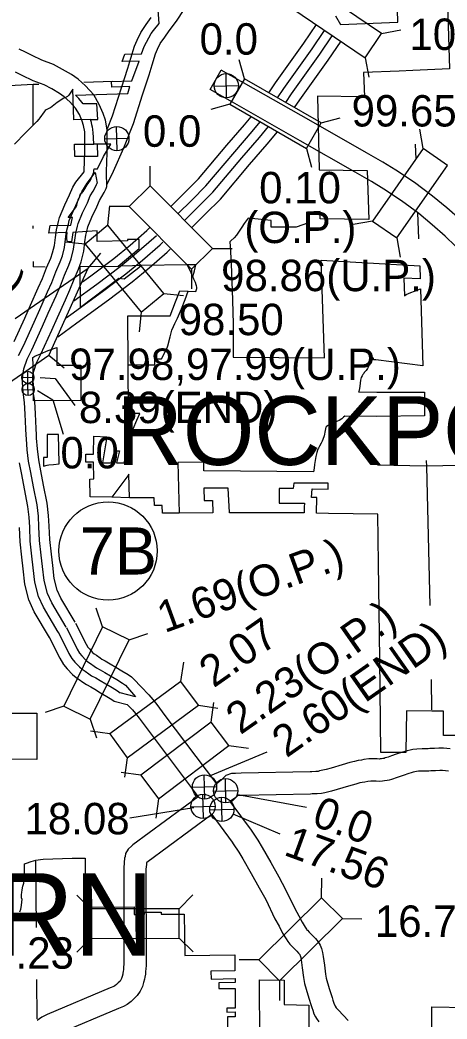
# Model space of a CAD drawing. Extents: x 369523 to 838377, y 495025 to 936819.
# Drawn here: x 655053 to 666534, y 860745 to 887609 of the extents above; entities that cross this region are included whole.
import ezdxf

# ---------------------------------------------------------------- set-up
doc = ezdxf.new("R2010")
doc.units = 0
for name, color, linetype in [('DSN_BRDG_Annotation', 7, 'Continuous'), ('DSN_DRFT_Common-Annotations', 7, 'Continuous'), ('DSN_DRFT_Common-Line', 7, 'Continuous'), ('DSN_DRFT_Junk-No-Plot', 7, 'Continuous'), ('Level 1', 7, 'Continuous'), ('Level 11', 7, 'Continuous'), ('Level 15', 7, 'Continuous'), ('Level 2', 7, 'Continuous'), ('Level 21', 7, 'Continuous'), ('Level 22', 7, 'Continuous'), ('Level 23', 7, 'Continuous')]:
    doc.layers.add(name, color=color, linetype=linetype)

msp = doc.modelspace()

# ---------------------------------------------------------------- linework, layer by layer
at = {"layer": 'DSN_BRDG_Annotation'}
for p, q in [((660171, 867293), (661699, 867933)), ((662759, 866430), (660911, 866775)), ((658003, 866159), (659728, 866430)), ((662044, 865715), (660787, 866258))]:
    msp.add_line(p, q, dxfattribs=at)
for points in [[(655592, 877992), (655997, 877970), (656531, 877244)], [(655527, 877650), (655933, 877393), (656211, 876475)]]:
    msp.add_lwpolyline(points, dxfattribs=at)
at = {"layer": 'DSN_DRFT_Common-Annotations'}
for p, q in [((660607, 885514), (660592, 886165)), ((660274, 885832), (660925, 885847)), ((657666, 884095), (657651, 884746)), ((657333, 884413), (657984, 884428)), ((655102, 877995), (655427, 878002)), ((655268, 877836), (655261, 878161)), ((655108, 877667), (655434, 877675)), ((655275, 877508), (655267, 877834)), ((660023, 866662), (660008, 867313)), ((660590, 866558), (660575, 867209)), ((659690, 866980), (660341, 866995)), ((659984, 866137), (659969, 866788)), ((660257, 866876), (660908, 866891)), ((660489, 866056), (660474, 866707)), ((659651, 866455), (660302, 866470)), ((660156, 866374), (660807, 866389))]:
    msp.add_line(p, q, dxfattribs=at)
for centre, radius in [((660599, 885840), 326), ((657658, 884421), 326), ((655265, 877999), 163), ((655271, 877671), 163), ((660015, 866987), 326), ((660583, 866884), 326), ((659976, 866463), 326), ((660481, 866381), 326)]:
    msp.add_circle(centre, radius, dxfattribs=at)
at = {"layer": 'DSN_DRFT_Common-Line'}
msp.add_circle((657422, 873331), 1320, dxfattribs=at)
at = {"layer": 'Level 1'}
for points in [[(657390, 883173), (657564, 883546), (657845, 884175), (658101, 884825), (658351, 885598), (658526, 886135), (658607, 886407), (658699, 886700), (658751, 886822), (658825, 886976), (658943, 887149), (659062, 887321), (659265, 887577), (659471, 887889)], [(657402, 884687), (657536, 885028), (657781, 885783), (657953, 886313), (658033, 886583), (658136, 886908), (658204, 887070), (658304, 887277), (658448, 887488), (658579, 887678)], [(660694, 866594), (661272, 865823), (661302, 865766), (661445, 865557), (661566, 865353), (661795, 864958), (662012, 864565), (662193, 864229), (662442, 863719), (662551, 863521), (662636, 863348), (662719, 863215), (662753, 863160), (662760, 863151), (662780, 863132), (662828, 863083), (662926, 862986), (662995, 862912), (663070, 862823), (663123, 862727), (663158, 862641), (663188, 862531), (663207, 862425), (663236, 862194), (663265, 861954), (663285, 861844), (663370, 861562), (663399, 861456), (663444, 861321), (663466, 861251), (663495, 861173), (663514, 861109), (663515, 861108), (663526, 861091), (663556, 861048), (663621, 860979), (663876, 860708)], [(660208, 866242), (660762, 865502), (660786, 865456), (660939, 865234), (661048, 865049), (661273, 864662), (661485, 864277), (661659, 863955), (661909, 863443), (662019, 863244), (662112, 863055), (662210, 862899), (662254, 862827), (662305, 862757), (662358, 862705), (662404, 862659), (662496, 862567), (662545, 862515), (662573, 862482), (662581, 862467), (662588, 862450), (662602, 862400), (662613, 862334), (662640, 862121), (662672, 861865), (662701, 861704), (662794, 861396), (662825, 861282), (662873, 861138), (662898, 861057), (662927, 860980), (662954, 860888), (662995, 860806), (663029, 860755), (663086, 860672)]]:
    msp.add_lwpolyline(points, dxfattribs=at)
at = {"layer": 'Level 11'}
for points in [[(657377, 883498), (657391, 883823), (657394, 884001), (657400, 884154), (657398, 884309), (657395, 884434), (657393, 884659), (657348, 884916), (657291, 885096), (657186, 885339), (657035, 885598), (656816, 885838), (656616, 886017), (656440, 886141), (656200, 886281), (655950, 886413), (655644, 886526), (655379, 886654), (655198, 886748), (655032, 886823)], [(666763, 881526), (666487, 881792), (666138, 882103), (665773, 882403), (665312, 882746), (664838, 883064), (664506, 883267), (664067, 883516), (662584, 884363), (660768, 885399), (660169, 885739), (660465, 886261)], [(666895, 882232), (666529, 882559), (666143, 882875), (665658, 883237), (665161, 883569), (664811, 883784), (664365, 884038), (662881, 884884), (661065, 885920), (660465, 886261)], [(656778, 883523), (656791, 883841), (656794, 884019), (656800, 884163), (656798, 884297), (656795, 884424), (656793, 884604), (656763, 884773), (656728, 884887), (656650, 885068), (656549, 885240), (656393, 885411), (656242, 885547), (656116, 885636), (655909, 885756), (655705, 885864), (655409, 885973), (655111, 886118), (654936, 886207)], [(656551, 883246), (656778, 883523)], [(656857, 883221), (657077, 883511), (657126, 883221)], [(657386, 883132), (657377, 883498)], [(654897, 878968), (655179, 879594), (655332, 879939), (655545, 880407), (655655, 880659), (655767, 880944), (655878, 881205), (655929, 881344), (655980, 881547), (656008, 881756), (656037, 881968), (656087, 882186), (656115, 882302), (656259, 882637), (656386, 882909), (656473, 883117), (656551, 883246)], [(655011, 878589), (655145, 878849), (655430, 879482), (655583, 879827), (655796, 880295), (655910, 880553), (656021, 880840), (656134, 881104), (656192, 881263), (656250, 881494), (656281, 881719), (656308, 881919), (656354, 882123), (656377, 882215), (656510, 882524), (656638, 882797), (656719, 882992), (656857, 883221)], [(656297, 871278), (655905, 871933), (655791, 872190), (655700, 872538), (655659, 872909), (655622, 873218), (655580, 873617), (655564, 873984), (655548, 874265), (655513, 874569), (655418, 875052), (655345, 875437), (655284, 875744), (655248, 876052), (655225, 876347), (655218, 876441), (655209, 876615), (655193, 877008), (655178, 877319), (655147, 877527), (655130, 877708), (655121, 877885), (655126, 878059), (655158, 878233), (655242, 878492), (655370, 878740), (655658, 879380), (655811, 879724), (656024, 880193), (656141, 880458), (656253, 880746), (656366, 881013), (656431, 881190), (656496, 881447), (656528, 881685), (656554, 881874), (656598, 882066), (656615, 882135), (656738, 882422), (656866, 882696), (656943, 882879), (657018, 883003), (657071, 883101), (657112, 883182), (657126, 883221)], [(656533, 871419), (656149, 872060), (656051, 872281), (655971, 872588), (655932, 872940), (655896, 873249), (655854, 873638), (655839, 873998), (655823, 874288), (655785, 874612), (655688, 875104), (655615, 875489), (655556, 875786), (655522, 876079), (655499, 876367), (655493, 876457), (655484, 876628), (655468, 877020), (655452, 877346), (655420, 877560), (655404, 877727), (655397, 877888), (655400, 878031), (655425, 878165), (655497, 878386), (655618, 878620), (655910, 879268), (656062, 879612), (656275, 880081), (656395, 880352), (656508, 880642), (656622, 880911), (656694, 881109), (656766, 881394), (656801, 881647), (656825, 881825), (656865, 882003), (656876, 882048), (656989, 882309), (657118, 882584), (657189, 882754), (657256, 882866), (657315, 882972), (657367, 883075), (657386, 883132)], [(656083, 871149), (655682, 871818), (655554, 872107), (655453, 872492), (655410, 872880), (655374, 873190), (655330, 873599), (655314, 873972), (655299, 874244), (655266, 874531), (655172, 875005), (655100, 875389), (655037, 875705)], [(655847, 871008), (655438, 871691), (655294, 872016), (655182, 872442), (655137, 872849), (655100, 873160), (655056, 873578), (655040, 873958)], [(656302, 871269), (656589, 870692), (656651, 870584), (656714, 870512), (656819, 870399), (656880, 870350), (656948, 870301), (657045, 870233), (657108, 870188), (657210, 870138), (657336, 870063), (657487, 869970), (657655, 869873), (657811, 869778), (657889, 869723)], [(656548, 871391), (656831, 870822), (656875, 870744), (656918, 870696), (657007, 870601), (657047, 870569), (657108, 870525), (657205, 870457), (657250, 870425), (657341, 870380), (657479, 870298), (657629, 870205), (657795, 870109), (657961, 870008), (658048, 869947)], [(655832, 871035), (656125, 870445), (656221, 870276), (656326, 870158), (656461, 870013), (656563, 869932), (656644, 869873), (656741, 869805), (656838, 869736), (656960, 869676), (657064, 869614), (657218, 869519), (657387, 869421), (657523, 869338), (657587, 869294)], [(656078, 871158), (656368, 870575), (656446, 870437), (656529, 870343), (656649, 870215), (656729, 870151), (656803, 870098), (656900, 870029), (656979, 869972), (657091, 869918), (657207, 869849), (657359, 869755), (657527, 869657), (657674, 869569), (657745, 869518)], [(658048, 869947), (658375, 869613)], [(657889, 869723), (658157, 869408), (657745, 869518)], [(658375, 869613), (658455, 869529), (658485, 869498), (658521, 869463), (658622, 869339), (658731, 869205), (658951, 868906), (660334, 867073)], [(657587, 869294), (657938, 869203)], [(657938, 869203), (658022, 869114), (658061, 869073), (658078, 869057), (658156, 868961), (658256, 868838), (658470, 868547), (659848, 866721)], [(666619, 868006), (666441, 868028), (666317, 868026), (666197, 868019), (666076, 868015), (666023, 868013), (665962, 868012), (665870, 868010), (665719, 868005), (665615, 867993), (665545, 867979), (665463, 867960), (665397, 867939), (665334, 867921), (665166, 867865), (665045, 867823), (664948, 867787), (664916, 867777), (664875, 867764), (664842, 867755), (664813, 867749), (664772, 867742), (664740, 867739), (664718, 867737), (664660, 867742), (664553, 867745), (664428, 867743), (664298, 867721), (664231, 867709), (664145, 867698), (664044, 867674), (663919, 867642), (663715, 867579), (663417, 867493), (663283, 867454), (663110, 867415), (663067, 867404), (663005, 867399), (662897, 867396), (662853, 867395), (661003, 867355), (660851, 867348), (660742, 867343), (660591, 867289), (660466, 867168), (660334, 867073)], [(666572, 867407), (666409, 867427), (666337, 867426), (666222, 867420), (666102, 867416), (666044, 867413), (665973, 867412), (665885, 867410), (665764, 867406), (665710, 867400), (665672, 867392), (665622, 867381), (665569, 867364), (665509, 867347), (665359, 867297), (665249, 867259), (665144, 867220), (665096, 867205), (665042, 867188), (664979, 867171), (664921, 867159), (664855, 867148), (664802, 867142), (664720, 867134), (664626, 867143), (664550, 867145), (664483, 867143), (664401, 867130), (664321, 867115), (664251, 867107), (664189, 867092), (664083, 867064), (663886, 867004), (663583, 866916), (663432, 866873), (663246, 866830), (663162, 866810), (663040, 866800), (662912, 866796), (662864, 866795), (661022, 866755), (660897, 866750), (660852, 866706), (660694, 866594)], [(659848, 866721), (658090, 865427), (658060, 865401), (657964, 865315), (657893, 865195), (657877, 865115), (657864, 865073), (657855, 864953), (657841, 864802), (657847, 862386), (657844, 862221), (657839, 862136), (657834, 862080), (657830, 862024), (657822, 861976), (657817, 861951), (657801, 861892), (657784, 861835), (657767, 861800), (657743, 861766), (657696, 861717), (657646, 861669), (657606, 861638), (657580, 861623), (657480, 861584), (655784, 860871), (655697, 860826), (655644, 860791), (655518, 860705)], [(660208, 866242), (658460, 864954), (658457, 864951), (658453, 864903), (658441, 864774), (658447, 862381), (658444, 862197), (658437, 862090), (658432, 862033), (658426, 861953), (658413, 861872), (658403, 861817), (658378, 861727), (658346, 861619), (658286, 861492), (658205, 861380), (658122, 861294), (658038, 861212), (657936, 861136), (657840, 861081), (657706, 861028), (656040, 860328)]]:
    msp.add_lwpolyline(points, dxfattribs=at)
at = {"layer": 'Level 15'}
for points in [[(655560, 885878), (655403, 885871), (654922, 885847), (649866, 885610), (649393, 885593), (647659, 885500)], [(657548, 885959), (656772, 885927)]]:
    msp.add_lwpolyline(points, dxfattribs=at)
at = {"layer": 'Level 2'}
for points in [[(663536, 887724), (663666, 887491), (665211, 887547), (665176, 888868)], [(666524, 888911), (666599, 886299), (665612, 886250), (665246, 886232), (664293, 886201)], [(657022, 884599), (657016, 884636), (657010, 884674), (657002, 884724), (656989, 884789), (656977, 884849), (656953, 884929), (657143, 884929), (657121, 885358), (656754, 885352), (656718, 885403), (656637, 885501), (656549, 885585), (657949, 885631), (658002, 885817), (657522, 885801), (657517, 885951), (658061, 885973), (658258, 886504), (657803, 886497), (657871, 886689), (658324, 886702), (658353, 886798), (658393, 886895), (658579, 887243), (658643, 887322), (658796, 887517), (658712, 888610)], [(664293, 886201), (664316, 885546), (663048, 885562), (663095, 883581), (664387, 883565), (664434, 882244), (663126, 882261), (663122, 882458), (662779, 882443), (662806, 882152), (662474, 882037), (661810, 882040), (661807, 882218), (661191, 882283), (661079, 882136), (661022, 882040), (660871, 881827), (660811, 881750), (660724, 881667), (660695, 881641), (660705, 881525), (660731, 881051), (660767, 880084), (660774, 879734), (660781, 879457), (660784, 878787), (660781, 878541), (663238, 878527), (663153, 881147), (665805, 880996), (665816, 880646), (665373, 880671), (665395, 880195), (665439, 880225), (665559, 880280), (665659, 880320), (665824, 880378), (665886, 878311), (664622, 878467), (664555, 878471), (664554, 878519), (664506, 878519), (664421, 878295), (664394, 878235), (664356, 878180), (664328, 878148), (664311, 878128), (664294, 878105), (664272, 878074), (664249, 878038), (664229, 878000), (664214, 877964), (664207, 877927), (664189, 877762), (664180, 877702), (664161, 877622), (664157, 877609), (664647, 877604), (665927, 877600), (665929, 876965), (664651, 876949), (663784, 876958), (663750, 876926), (663702, 876887), (663631, 876841), (663543, 876799), (663428, 876749), (663373, 876721), (663337, 876703), (663296, 876676), (663283, 876667), (663280, 876657), (663258, 876572), (663227, 876429), (663195, 876330), (663178, 876284), (663155, 876234), (663108, 876152), (663075, 876099), (663062, 876067), (663054, 876041), (663038, 875983), (663010, 875867), (662970, 875655), (662964, 875562), (662944, 875458), (659999, 875489), (659995, 875717), (659294, 875712), (659331, 874348)], [(656953, 884929), (656498, 884928), (656474, 885745), (656400, 885643), (656362, 885584), (656349, 885571), (656327, 885556), (656216, 885494), (656148, 885451), (656053, 885389), (655874, 885251), (655845, 885234), (655792, 885210), (655754, 885190), (655730, 885172), (655702, 885143), (655590, 884981), (655559, 884938), (655508, 884883), (655456, 884826), (655397, 884770), (655198, 884578), (654905, 884268)], [(656977, 884849), (656953, 884929)], [(657039, 884269), (657022, 884599), (657016, 884636), (657010, 884674), (657002, 884724), (656989, 884789), (656977, 884849)], [(659331, 874348), (658881, 874346), (658876, 874556), (658666, 874555), (658660, 874764), (658000, 874761), (657983, 875395), (657955, 875353), (657522, 874774), (656940, 874790), (656930, 875266), (657042, 875267), (657033, 875723), (656824, 875721), (656825, 875930), (657033, 875931), (657035, 876414), (657385, 876403), (657274, 875699), (657505, 875701), (657607, 876026), (657731, 876027), (657651, 875702), (657851, 875703), (657931, 876028), (657966, 876128), (658097, 876617), (658192, 876847), (658275, 877028), (657967, 877027), (657961, 878334), (658681, 878336), (658680, 878496), (658859, 878497), (658966, 878708), (659017, 878820), (659027, 878851), (659089, 879086), (659107, 879161), (659137, 879267), (659178, 879366), (659219, 879444), (659287, 879591), (659392, 879839), (659395, 879846), (659492, 880095), (659574, 880318), (659778, 880311), (659803, 880364), (659807, 880390), (659806, 880427), (659800, 880457), (659790, 880490), (659769, 880547), (659725, 880642), (659698, 880708), (659743, 880868), (659782, 881029), (659548, 881025), (658318, 881004), (658081, 881000), (657689, 880993), (658254, 881468), (658254, 881707), (657944, 881702), (657944, 881669), (657129, 881655), (657125, 881936), (656477, 881896), (656442, 881644), (656329, 881642), (656316, 881722), (656316, 881789), (656322, 881891), (655832, 881876), (655861, 882084), (656417, 882092), (656465, 882301), (656347, 882302), (656469, 882446), (656568, 882589), (656582, 882632), (656621, 882769), (656647, 882821), (656679, 882935), (656724, 882968), (656751, 882995), (656799, 883066), (656860, 883175), (656953, 883303), (656998, 883409), (657035, 883519), (657042, 883563), (657047, 883609), (657134, 883609), (657302, 883939), (657499, 884270), (657127, 884269), (657039, 884269), (657022, 884599)], [(657689, 880993), (658254, 881468), (658254, 881707), (657944, 881702), (657944, 881669), (657129, 881655), (657125, 881936), (656477, 881896), (656442, 881644), (656329, 881642), (656316, 881722), (656316, 881789), (656322, 881891), (655832, 881876), (655861, 882084), (656417, 882092), (656465, 882301), (656347, 882302), (656469, 882446), (656568, 882589), (656582, 882632), (656621, 882769), (656647, 882821), (656679, 882935), (656724, 882968), (656751, 882995), (656799, 883066), (656860, 883175), (656953, 883303), (656998, 883409), (657035, 883519), (657042, 883563), (657047, 883609), (657134, 883609), (657302, 883939), (657499, 884270), (657127, 884269)], [(656518, 884268), (657039, 884269)], [(656528, 883938), (656518, 884268)], [(657127, 884269), (657140, 883939)], [(657140, 883939), (656528, 883938)], [(656672, 880976), (657689, 880993)], [(656678, 879876), (656672, 880976)], [(658249, 880946), (657856, 880639)], [(658318, 881004), (658249, 880946)], [(659548, 881025), (658318, 881004)], [(659698, 880708), (659685, 880741), (659643, 880838), (659596, 880932), (659548, 881025)], [(657710, 880654), (656678, 879876)], [(657856, 880639), (657710, 880654)], [(659725, 880642), (659698, 880708)], [(659769, 880547), (659725, 880642)], [(659790, 880490), (659769, 880547)], [(659778, 880311), (659803, 880364)], [(659800, 880457), (659790, 880490)], [(659806, 880427), (659800, 880457)], [(659803, 880364), (659807, 880390)], [(659807, 880390), (659806, 880427)], [(657961, 878334), (657954, 879655), (659094, 879658), (659235, 880032), (659348, 880326), (659574, 880318)], [(659574, 880318), (659778, 880311)], [(656692, 877373), (655412, 877369), (655403, 878326), (655401, 878534), (655448, 878565), (655606, 878635), (655807, 878722), (656042, 878805)], [(656042, 878805), (656045, 878328), (656686, 878330), (656692, 877373)], [(657967, 877027), (657961, 878334)], [(658275, 877028), (657967, 877027)], [(658097, 876617), (658192, 876847)], [(658192, 876847), (658275, 877028)], [(657966, 876128), (658097, 876617)], [(657033, 875931), (657035, 876414)], [(657035, 876414), (657385, 876403)], [(657385, 876403), (657274, 875699), (657505, 875701)], [(657931, 876028), (657966, 876128)], [(656824, 875721), (656825, 875930), (657033, 875931)], [(657505, 875701), (657607, 876026)], [(657607, 876026), (657731, 876027)], [(657731, 876027), (657651, 875702)], [(657851, 875703), (657931, 876028)], [(657033, 875723), (656824, 875721)], [(657042, 875267), (657033, 875723)], [(657651, 875702), (657851, 875703)], [(656930, 875266), (657042, 875267)], [(656940, 874790), (656930, 875266)], [(660650, 875019), (659994, 875016)], [(659994, 875016), (660001, 874689)], [(660683, 874365), (660650, 875019)], [(662402, 875007), (662017, 875010)], [(662017, 875010), (662022, 874619)], [(662412, 875157), (662402, 875007)], [(663336, 875156), (662412, 875157)], [(662887, 874768), (662905, 874999)], [(662905, 874999), (663338, 874996)], [(663338, 874996), (663336, 875156)], [(657522, 874774), (656940, 874790)], [(658000, 874761), (657522, 874774)], [(658660, 874764), (658000, 874761)], [(658666, 874555), (658660, 874764)], [(663037, 874765), (662887, 874768)], [(663021, 874350), (663037, 874765)], [(658876, 874556), (658666, 874555)], [(658881, 874346), (658876, 874556)], [(660001, 874689), (660231, 874690)], [(660231, 874690), (660238, 874353)], [(662022, 874619), (662703, 874618)], [(662696, 874506), (662693, 874356)], [(662703, 874618), (662696, 874506)], [(659331, 874348), (658881, 874346)], [(660238, 874353), (659331, 874348)], [(660683, 874356), (660683, 874365)], [(662655, 874357), (660683, 874356)], [(662693, 874356), (662655, 874357)], [(663347, 874340), (663021, 874350)], [(664670, 874320), (663347, 874340)], [(664689, 872990), (664670, 874320)], [(664726, 870429), (664689, 872990)], [(664751, 867915), (664726, 870429)], [(654538, 868970), (655506, 868970), (655505, 867891), (655505, 867725), (653738, 867738)], [(665446, 869030), (665431, 867910)], [(666123, 869025), (665446, 869030)], [(666438, 869026), (666123, 869025)], [(666443, 868372), (666438, 869026)], [(667070, 868367), (666443, 868372)], [(665431, 867910), (664751, 867915)], [(655048, 863625), (655072, 863702), (655093, 863797), (655105, 863892), (655110, 863956), (655098, 864006), (655091, 864046), (655096, 864094), (655101, 864144), (655110, 864222), (655132, 864315), (655155, 864394), (655170, 864541), (655177, 864705), (655177, 864806), (655172, 864914), (655228, 864938), (655355, 864984), (655419, 865000), (655477, 865013), (655542, 865025), (655605, 865036), (655677, 865042), (656458, 865070), (656577, 865072), (656637, 865073), (656699, 865073), (656744, 865074), (656773, 865071), (656804, 865069), (656809, 863755), (658121, 863766), (658125, 863556), (658404, 863558), (658403, 863618), (658852, 863622), (658853, 863562), (659465, 863566), (659483, 862450), (660829, 862467), (660832, 862043), (660186, 862029), (660191, 861820), (660834, 861834), (660835, 861724), (660401, 861720), (660402, 861563), (660836, 861567), (660840, 861039), (660613, 861037), (660613, 860932), (660840, 860934), (660841, 860804), (660631, 860803), (660634, 860488)], [(661504, 860148), (661493, 861801), (662152, 861791), (662156, 861132), (662816, 861122), (662820, 860459)], [(666118, 859750), (666128, 861070), (667071, 861057)]]:
    msp.add_lwpolyline(points, dxfattribs=at)
msp.add_lwpolyline([(656109, 875692), (656090, 876461), (655783, 876459), (655786, 875845), (655686, 875844), (655687, 875613), (655787, 875636), (655827, 875643), (655953, 875657), (656110, 875670)], close=True, dxfattribs=at)
at = {"layer": 'Level 21'}
for p, q in [((664776, 887244), (665295, 887342)), ((661088, 886028), (660950, 886538)), ((664331, 886589), (664430, 886070)), ((660693, 885342), (660183, 885204)), ((663147, 884843), (663657, 884981)), ((665893, 884152), (665801, 884672)), ((662752, 884157), (662890, 883647)), ((658553, 883153), (658555, 883681)), ((657418, 882088), (657469, 882613)), ((657991, 882595), (657463, 882597)), ((664535, 882203), (664015, 882110)), ((665185, 881750), (665278, 881231)), ((656806, 881585), (656280, 881637)), ((660227, 881467), (660755, 881465)), ((656889, 880934), (657227, 881339)), ((654927, 879578), (656889, 880934)), ((655833, 878588), (656889, 880934)), ((659665, 880909), (659663, 880381)), ((658925, 880251), (659451, 880199)), ((658313, 879749), (658261, 879223)), ((655833, 878588), (653873, 877238)), ((656239, 878250), (655833, 878588)), ((657275, 871289), (657103, 871789)), ((657986, 870942), (658486, 871113)), ((659381, 869819), (659461, 870341)), ((656231, 869155), (655732, 868984)), ((659851, 869181), (660373, 869102)), ((660195, 868731), (660269, 869254)), ((656943, 868807), (657114, 868308)), ((657468, 868410), (656946, 868489)), ((660672, 868099), (661195, 868025)), ((657938, 867772), (657859, 867250)), ((658299, 867300), (657776, 867373)), ((658776, 866667), (658703, 866145)), ((663163, 864007), (663166, 864535)), ((656956, 863706), (656581, 864078)), ((659332, 863712), (659704, 864087)), ((663720, 863444), (664248, 863442)), ((656958, 862914), (656585, 862540)), ((659334, 862920), (659708, 862548)), ((661474, 862335), (660946, 862338)), ((662032, 861773), (662029, 861245))]:
    msp.add_line(p, q, dxfattribs=at)
for points in [[(662366, 887925), (664331, 886589), (664776, 887244), (662812, 888580)], [(660693, 885342), (662752, 884157), (663147, 884843), (661088, 886028)], [(665185, 881750), (666543, 883700), (665893, 884152), (664535, 882203)], [(660227, 881467), (658553, 883153), (657991, 882595), (659665, 880909)], [(656806, 881585), (658313, 879749), (658925, 880251), (657418, 882088)], [(656943, 868807), (657986, 870942), (657275, 871289), (656231, 869155)], [(659381, 869819), (657468, 868410), (657938, 867772), (659851, 869181)], [(658776, 866667), (660672, 868099), (660195, 868731), (658299, 867300)], [(663163, 864007), (661474, 862335), (662032, 861773), (663720, 863444)], [(659332, 863712), (656956, 863706), (656958, 862914), (659334, 862920)]]:
    msp.add_lwpolyline(points, close=True, dxfattribs=at)
at = {"layer": 'Level 22'}
for points in [[(655404, 884775), (655403, 885871)], [(665680, 884268), (665694, 883867)], [(665745, 882432), (665771, 881723)], [(655408, 882000), (655408, 882078)], [(655407, 881112), (655405, 880968)], [(655731, 880961), (655405, 880968)], [(670891, 875710), (665975, 875615), (664666, 875637)], [(665976, 875760), (665982, 875601), (666068, 871861)], [(666107, 869871), (666114, 869058)], [(655466, 864989), (655484, 863202)], [(655498, 861810), (655509, 860748)]]:
    msp.add_lwpolyline(points, dxfattribs=at)
at = {"layer": 'Level 23'}
for points in [[(661741, 885652), (661924, 885923), (662681, 886987), (663025, 887492)], [(661980, 885515), (662150, 885766), (662907, 886830), (663243, 887324)], [(662197, 885390), (662355, 885623), (663112, 886687), (663447, 887180)], [(662436, 885252), (662581, 885466), (663338, 886530), (663685, 887040)], [(659105, 882590), (659477, 882960), (659850, 883335), (660616, 884243), (661089, 884786), (661271, 885009)], [(659299, 882396), (659671, 882766), (660053, 883149), (660825, 884064), (661299, 884608), (661513, 884870)], [(659476, 882219), (659848, 882589), (660237, 882980), (661015, 883901), (661490, 884447), (661732, 884744)], [(659670, 882025), (660042, 882394), (660440, 882794), (661223, 883722), (661701, 884270), (661974, 884605)], [(656738, 880568), (656956, 880727), (657577, 881199), (658012, 881556), (658466, 881949), (658536, 882020)], [(656504, 880057), (657120, 880506), (657748, 880984), (658189, 881345), (658654, 881748), (658721, 881816)], [(656070, 879089), (656584, 879466), (657434, 880085), (658073, 880572), (658527, 880944), (659014, 881365), (659092, 881444)], [(656299, 879598), (656422, 879688), (657269, 880306), (657903, 880787), (658350, 881154), (658826, 881566), (658892, 881633)]]:
    msp.add_lwpolyline(points, dxfattribs=at)

# ---------------------------------------------------------------- texts
at = {"layer": 'DSN_BRDG_Annotation'}
for s, p in [('0.0', (659882, 886677)), ('0.0', (658358, 884200)), ('8.39(END)', (656637, 876769)), ('0.0', (656141, 875551)), ('18.08', (655175, 865712))]:
    msp.add_text(s, height=844.8, dxfattribs=at).set_placement(p)
for s, rotation, p in [('2.60(END)', 35, (662217, 867753)), ('0.0', 340, (662868, 865963)), ('17.56', 340, (662113, 865166))]:
    msp.add_text(s, height=844.8, rotation=rotation, dxfattribs=at).set_placement(p)
at = {"layer": 'DSN_DRFT_Common-Annotations'}
for s, height, p in [('ROCKPORT', 1848, (657647, 875644)), ('MALVERN', 2217.6, (644311, 862449))]:
    msp.add_text(s, height=height, dxfattribs=at).set_placement(p)
at = {"layer": 'DSN_DRFT_Common-Line'}
msp.add_text('7B', height=1267.2, dxfattribs=at).set_placement((656662, 872698))
at = {"layer": 'DSN_DRFT_Junk-No-Plot'}
for s, p in [('100.22(U.P.)', (665524, 886803)), ('99.65(U.P.)', (663968, 884745)), ('0.10', (661483, 882679)), ('(O.P.)', (661085, 881610)), ('98.86(U.P.)', (660461, 880317)), ('98.50', (659318, 879134)), ('97.98,97.99(U.P.)', (656375, 877929)), ('16.72', (664594, 862955)), ('17.23', (653676, 862098))]:
    msp.add_text(s, height=844.8, dxfattribs=at).set_placement(p)
for s, rotation, p in [('8.20(O.P.)', 310, (651287, 884054)), ('1.69(O.P.)', 20, (658941, 871119)), ('2.23(O.P.)', 35, (660978, 868373)), ('2.07', 35, (660259, 869634))]:
    msp.add_text(s, height=844.8, rotation=rotation, dxfattribs=at).set_placement(p)

doc.saveas('drawing.dxf')
